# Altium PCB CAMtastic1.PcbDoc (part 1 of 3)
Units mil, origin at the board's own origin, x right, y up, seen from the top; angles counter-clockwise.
Board outline 2031.62 x 893.83 mil, 4 copper layers (Top Layer, Mid-Layer 1, Mid-Layer 2, Bottom Layer); 0 components, 63 nets, 248 pads, 0 vias.
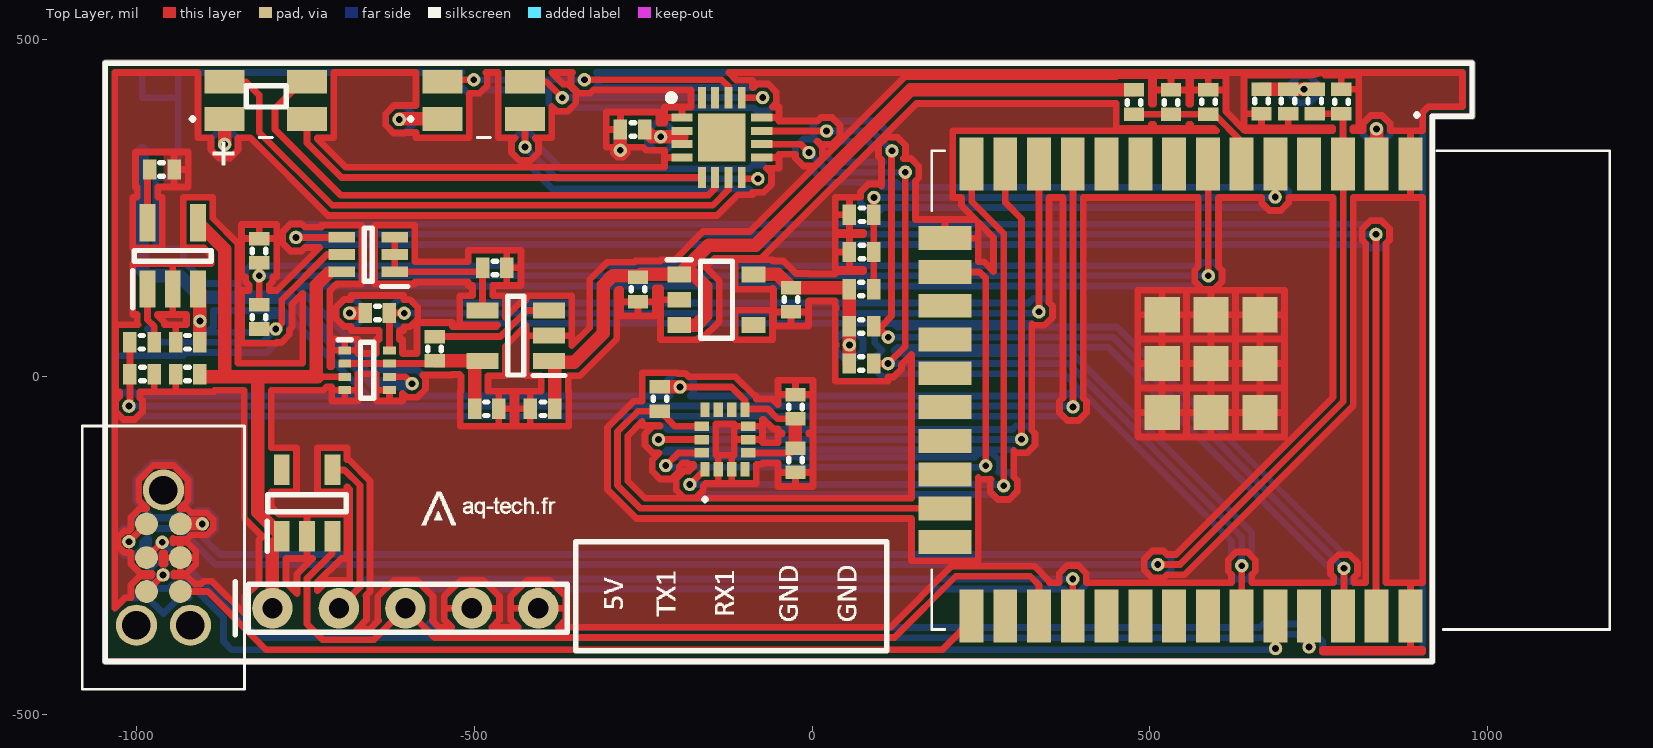
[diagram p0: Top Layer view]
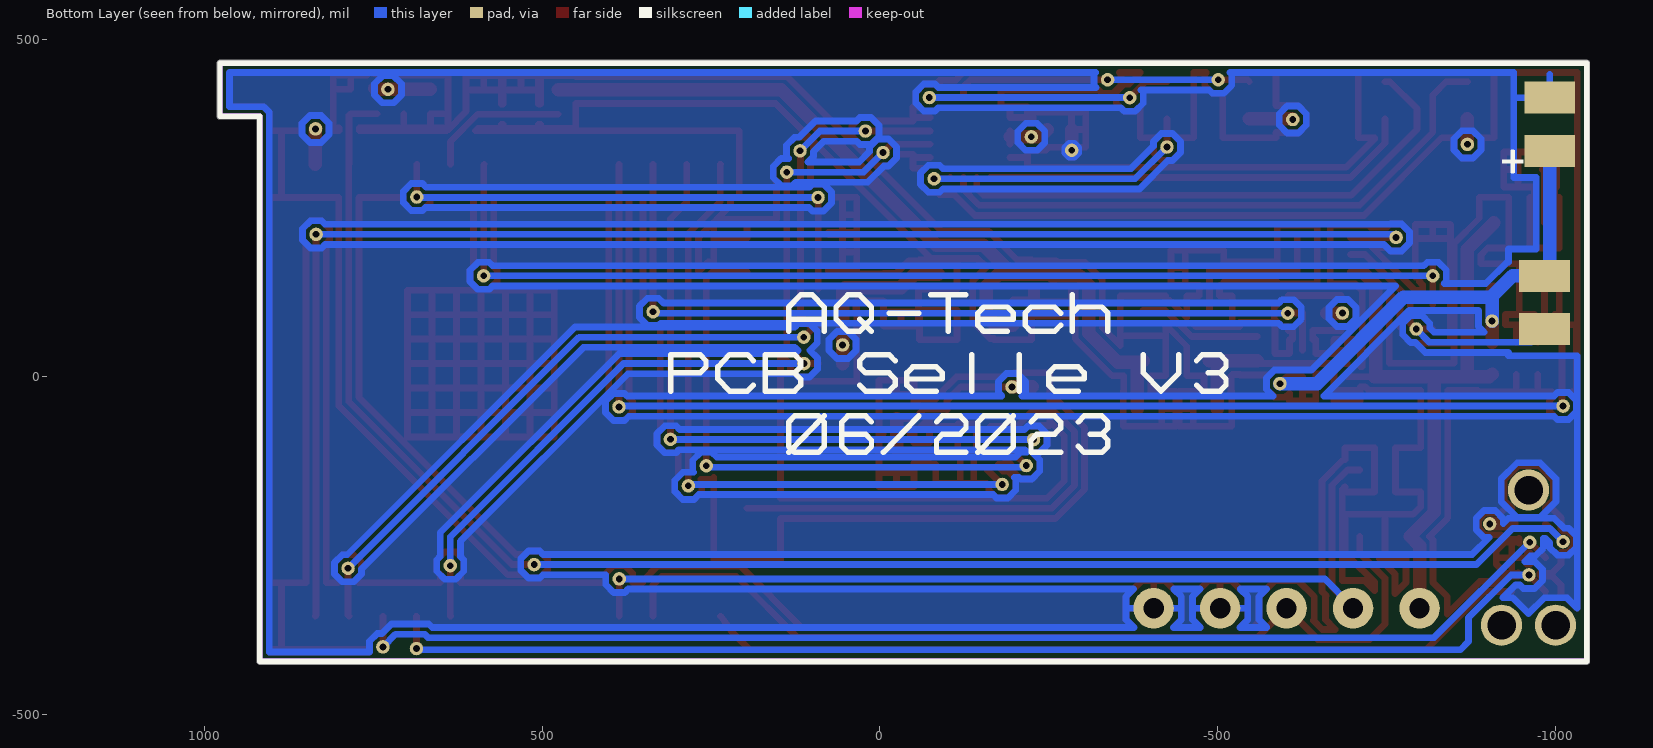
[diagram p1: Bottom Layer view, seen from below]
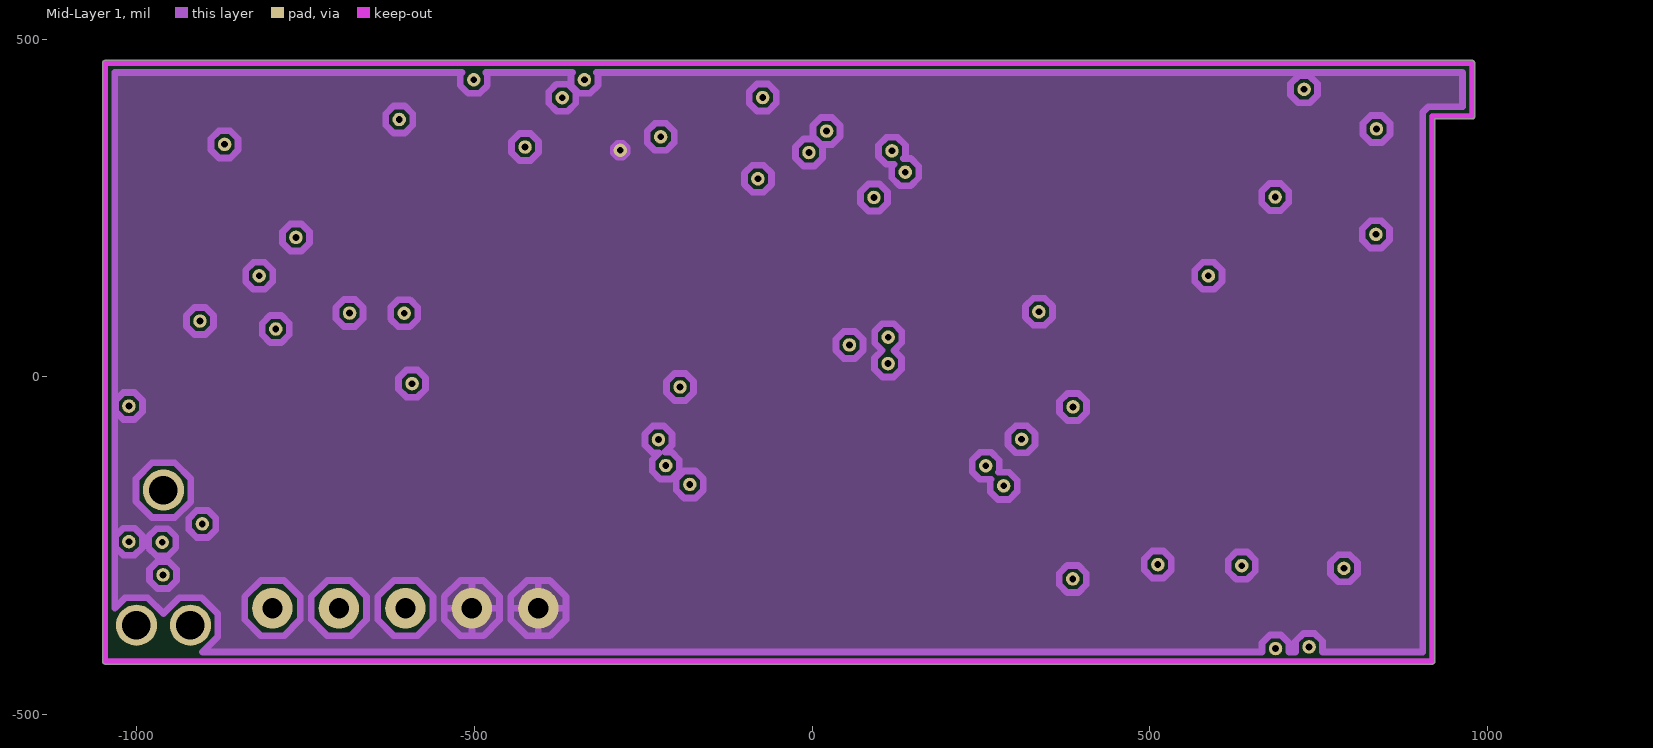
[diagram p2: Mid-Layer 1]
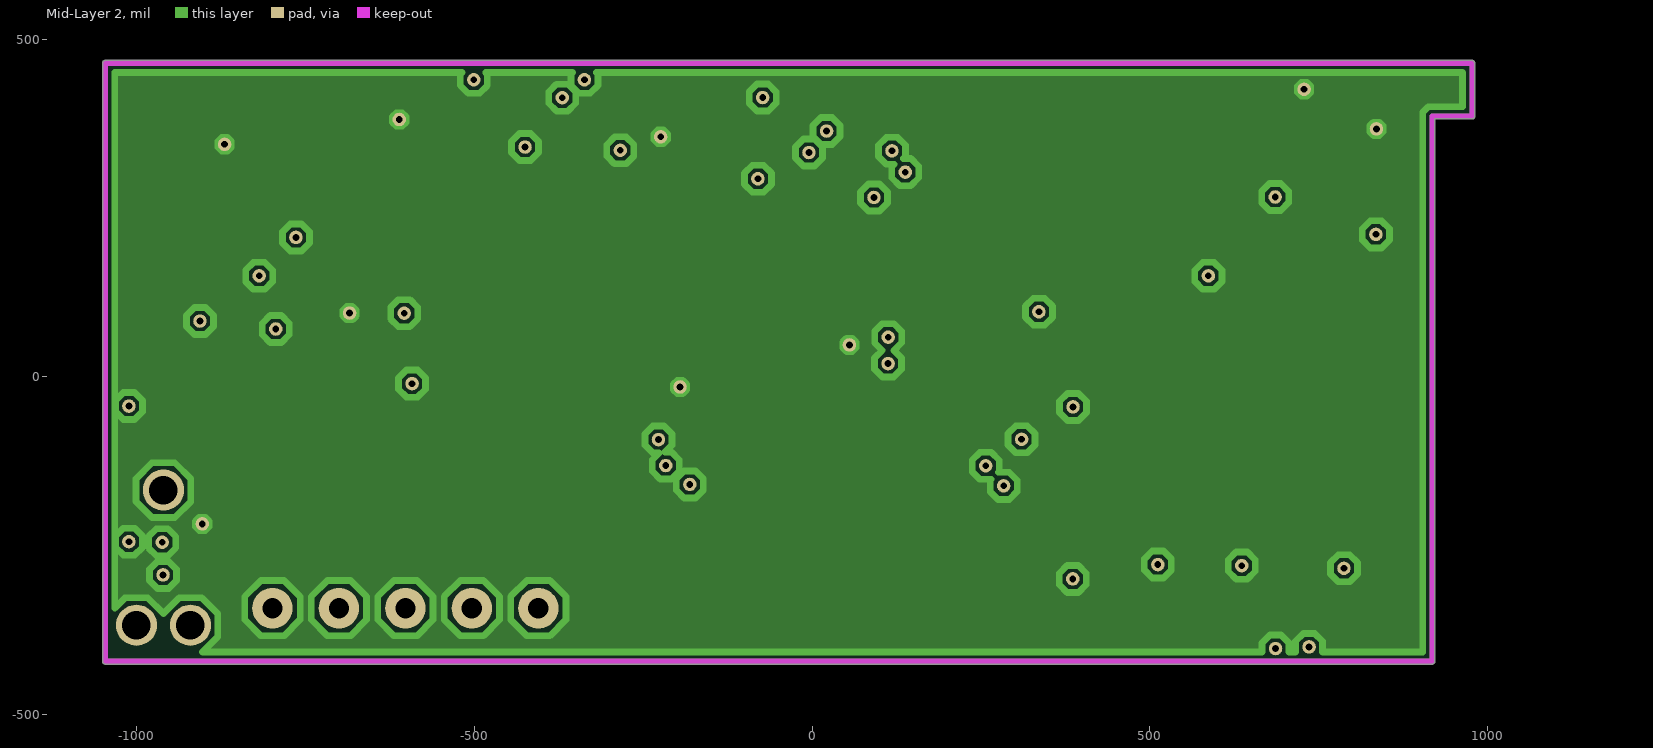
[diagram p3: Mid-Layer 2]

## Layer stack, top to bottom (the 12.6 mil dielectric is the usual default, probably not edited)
Top Solder: solder mask 0.4, Solder Resist, Dk 3.5
Top Layer: signal copper 1.4
Dielectric 1: dielectric 12.6, FR-4, Dk 4.8
Mid-Layer 1: signal copper 1.4
Dielectric 2: dielectric 12.6, FR-4, Dk 4.8
Mid-Layer 2: signal copper 1.4
Dielectric 3: dielectric 12.6, FR-4, Dk 4.8
Bottom Layer: signal copper 1.4
Bottom Solder: solder mask 0.4, Solder Resist, Dk 3.5

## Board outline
-1050.68,-421.26 -1050.68,464.57 cw(c-1046.68,464.57) -1046.68,468.57 976.94,468.57 cw(c976.94,464.57) 980.94,464.57 980.94,385.83 cw(c976.94,385.83) 976.94,381.83 921.89,381.83 921.89,-421.26 cw(c917.89,-421.26) 917.89,-425.26 -1046.68,-425.26 cw(c-1046.68,-421.26)

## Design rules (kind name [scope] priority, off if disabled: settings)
Clearance [All] p1: gap=10 ignorepadtopadclearanceinfootprint=FALSE except(0: Arc-Hole Track-Hole SMDPad-Hole THPad-Hole Via-Hole Fill-Hole Poly-Hole Region-Hole Text-Hole)
PolygonConnect CAM_PolygonConnect_$Net0 [InNet('$Net0')] p1: connectstyle=Direct reliefconductorwidth=10 reliefentries=4 polygonreliefangle="90 Angle" airgapwidth=10
PolygonConnect CAM_PolygonConnect_$Net11 [InNet('$Net11')] p2: connectstyle=Direct reliefconductorwidth=10 reliefentries=4 polygonreliefangle="90 Angle" airgapwidth=10
PolygonConnect [All] p3: connectstyle=Relief reliefconductorwidth=10 reliefentries=4 polygonreliefangle="90 Angle" airgapwidth=10
RoutingVias [All] p1: holewidth=28 width=50 viastyle="Through Hole" minholewidth=28 minwidth=50 maxholewidth=28 maxwidth=50
SolderMaskExpansion [All] p1: expansion=4 istentingtop=FALSE
Width [All] p1: maxlimit=10 minlimit=10 preferedwidth=10
30 further rules are at their usual default settings.

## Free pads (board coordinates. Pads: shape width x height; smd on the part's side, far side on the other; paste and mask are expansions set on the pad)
  round 20 hole 10 mask+24: 1(-1011.81,-244.09) 1(-1011.81,-43.31) 1(-962.48,-244.91) 1(-961.23,-293.31) 1(-906.55,82.68) 1(-903.06,-217.79) 1(-870.06,344.25) 1(-818.9,149.61) 1(-794.33,70.87) 1(-764.5,206.49) 1(-685.04,94.49) 1(-611.52,381.09) 1(-604.13,94.25) 1(-592.46,-10.03) 1(-501.11,439.92) 1(-425.21,340.32) 1(-370.08,413.39) 1(-337.31,439.92) 1(-284.16,335.43) 1(-227.65,-92.85) 1(-224.41,355.38) 1(-216.87,-131.27) 1(-195.71,-15.01) 1(-181.26,-159.32) 1(-80.36,293.32) 1(-73.4,413.63) 1(-4.77,332.17) 1(21.28,364.01) 1(55.12,47.24) 1(91.47,265.6) 1(112.33,19.63) 1(112.48,58.77) 1(118.11,334.65) 1(137.8,303.15) 1(256.91,-131.72) 1(283.46,-161.42) 1(310.04,-92.45) 1(335.66,96.4) 1(385.83,-299.21) 1(386.19,-44.46) 1(511.81,-278) 1(586.61,149.61) 1(636.01,-279.53) 1(685.53,266.32) 1(686.04,-402.28) 1(728.35,425.76) 1(735.7,-399.84) 1(787.4,-283.46) 1(834.65,210.98) 1(835.5,367.15)
  rect 20x30 smd paste+0 mask+24: 1(-1010.18,3.94) 1(-1010.18,51.18) 1(-980.88,307.09) 1(-974.18,3.94) 1(-974.18,51.18) 1(-944.88,307.09) 1(-942.55,3.94) 1(-942.55,51.18) 1(-906.55,3.94) 1(-906.55,51.18) 1(-661.98,94.49) 1(-625.98,94.49) 1(-500,-47.24) 1(-488.19,161.42) 1(-464,-47.24) 1(-452.19,161.42) 1(-417.32,-47.24) 1(-381.32,-47.24) 1(-284.03,366.14) 1(-248.03,366.14) 1(55.12,19.63) 1(55.12,74.74) 1(55.12,129.86) 1(55.12,184.98) 1(55.12,240.1) 1(91.12,19.63) 1(91.12,74.74) 1(91.12,129.86) 1(91.12,184.98) 1(91.12,240.1)
  round 61.02 hole 42.13 mask+3.49: 1(-1000.63,-367.72) 1(-960.63,-167.72) 1(-920.63,-367.72)
  rect 74.8x47.24 smd far side paste+0 mask-3.4: 1(-992.13,334.65) 1(-992.13,413.39) 1(-984.25,70.87) 1(-984.25,149.61)
  round 33.86 smd paste+0 mask+17.07: 1(-985.63,-317.72) 1(-985.63,-267.72) 1(-985.63,-217.72) 1(-935.63,-317.72) 1(-935.63,-267.72) 1(-935.63,-217.72)
  rect 23.62x55.12 smd paste+0 mask+22.19: 1(-984.25,129.92) 1(-984.25,228.35) 1(-946.85,129.92) 1(-909.45,129.92) 1(-909.45,228.35)
  rect 59.05x35.43 smd paste+0 mask+4.47: 1(-870.08,381.89) 1(-870.08,437.01) 1(-748.03,381.89) 1(-748.03,437.01) 1(-547.24,381.89) 1(-547.24,437.01) 1(-425.2,381.89) 1(-425.2,437.01)
  rect 30x20 smd paste+0 mask+19: 1(-818.9,70.87) 1(-818.9,106.87) 1(-818.9,168.72) 1(-818.9,204.72) 1(-559.06,23.62) 1(-559.06,59.62) 1(-257.87,111.13) 1(-257.87,147.13) 1(-225.59,-50.96) 1(-225.59,-14.96) 1(-31.5,96.17) 1(-31.5,132.17) 1(-24.8,-141.51) 1(-24.8,-105.51) 1(-24.8,-62.2) 1(-24.8,-26.2) 1(476.32,388.91) 1(476.32,424.91) 1(531.44,388.91) 1(531.44,424.91) 1(586.55,388.91) 1(586.55,424.91) 1(665.35,389.76) 1(665.35,425.76) 1(704.72,389.76) 1(704.72,425.76) 1(744.09,389.76) 1(744.09,425.76) 1(783.46,389.76) 1(783.46,425.76)
  round 60 hole 30 mask+4: 1(-799.21,-342.52) 1(-700.79,-342.52) 1(-602.36,-342.52) 1(-503.94,-342.52) 1(-405.51,-342.52)
  rect 23.62x45.28 smd paste+0 mask+22.19: 1(-785.43,-236.22) 1(-785.43,-137.8) 1(-748.03,-236.22) 1(-710.63,-236.22) 1(-710.63,-137.8)
  rect 39.37x15.75 smd paste+0 mask+14.31: 1(-696.85,155.51) 1(-696.85,181.1) 1(-696.85,206.69) 1(-618.11,155.51) 1(-618.11,181.1) 1(-618.11,206.69)
  rect 18.9x11.81 smd paste+0 mask+24.55: 1(-692.13,-19.69) 1(-692.13,0) 1(-692.13,19.68) 1(-692.13,39.37) 1(-625.98,-19.69) 1(-625.98,0) 1(-625.98,19.68) 1(-625.98,39.37)
  rect 47.24x23.62 smd paste+0 mask+10.38: 1(-488.19,23.62) 1(-488.19,98.43) 1(-389.76,23.62) 1(-389.76,61.02) 1(-389.76,98.43)
  rect 35.43x23.62 smd paste+0 mask+16.28: 1(-196.85,76.77) 1(-196.85,114.17) 1(-196.85,151.57) 1(-86.61,76.77) 1(-86.61,151.57)
  rect 31.5x11.81 smd paste+0 mask+18.25: 1(-192.91,324.8) 1(-192.91,344.49) 1(-192.91,364.17) 1(-192.91,383.86) 1(-74.8,324.8) 1(-74.8,344.49) 1(-74.8,364.17) 1(-74.8,383.86)
  rect 21.65x13.78 smd paste+0 mask+23.17: 1(-163.78,-112.6) 1(-163.78,-92.91) 1(-163.78,-73.23) 1(-94.49,-112.6) 1(-94.49,-92.91) 1(-94.49,-73.23)
  rect 11.81x31.5 smd paste+0 mask+28.09: 1(-163.39,295.28) 1(-163.39,413.39) 1(-143.7,295.28) 1(-143.7,413.39) 1(-124.02,295.28) 1(-124.02,413.39) 1(-104.33,295.28) 1(-104.33,413.39)
  rect 13.78x21.65 smd paste+0 mask+27.11: 1(-158.66,-137.01) 1(-158.66,-48.82) 1(-138.98,-137.01) 1(-138.98,-48.82) 1(-119.29,-137.01) 1(-119.29,-48.82) 1(-99.61,-137.01) 1(-99.61,-48.82)
  rect 70.87x70.87 smd paste+0 mask-1.43: 1(-133.86,354.33)
  rect 78.74x35.43 smd paste+0 mask-5.37: 1(196.46,-244.69) 1(196.46,-194.69) 1(196.46,-144.69) 1(196.46,-94.69) 1(196.46,-44.69) 1(196.46,5.31) 1(196.46,55.31) 1(196.46,105.31) 1(196.46,155.31) 1(196.46,205.31)
  rect 35.43x78.74 smd paste+0 mask+16.28: 1(235.83,-354.33) 1(235.83,314.96) 1(285.83,-354.33) 1(285.83,314.96) 1(335.83,-354.33) 1(335.83,314.96) 1(385.83,-354.33) 1(385.83,314.96) 1(435.83,-354.33) 1(435.83,314.96) 1(485.83,-354.33) 1(485.83,314.96) 1(535.83,-354.33) 1(535.83,314.96) 1(585.83,-354.33) 1(585.83,314.96) 1(635.83,-354.33) 1(635.83,314.96) 1(685.83,-354.33) 1(685.83,314.96) 1(735.83,-354.33) 1(735.83,314.96) 1(785.83,-354.33) 1(785.83,314.96) 1(835.83,-354.33) 1(835.83,314.96) 1(885.83,-354.33) 1(885.83,314.96)
  rect 52.36x52.36 smd paste+0 mask+7.82: 1(518.11,-52.76) 1(518.11,19.68) 1(518.11,92.13) 1(590.55,-52.76) 1(590.55,19.68) 1(590.55,92.13) 1(662.99,-52.76) 1(662.99,19.68) 1(662.99,92.13)

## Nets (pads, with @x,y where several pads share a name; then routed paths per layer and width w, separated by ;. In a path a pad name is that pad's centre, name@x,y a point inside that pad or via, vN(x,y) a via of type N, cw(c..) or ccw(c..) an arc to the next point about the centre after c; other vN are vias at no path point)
$Net0: pad.1@55.12,19.63 pad.1@55.12,47.24 pad.1@55.12,74.74 pad.1@55.12,129.86 pad.1@665.35,425.76 pad.1@704.72,425.76 pad.1@728.35,425.76 pad.1@744.09,425.76 pad.1@835.5,367.15 pad.1@835.83,314.96 pad.1@-24.8,-62.2 pad.1@-24.8,-105.51 pad.1@-31.5,132.17 pad.1@-86.61,151.57 pad.1@-94.49,-112.6 pad.1@-99.61,-48.82 pad.1@-192.91,344.49 pad.1@-192.91,364.17 pad.1@-195.71,-15.01 pad.1@-224.41,355.38 pad.1@-225.59,-14.96 pad.1@-248.03,366.14 pad.1@-547.24,381.89 pad.1@-611.52,381.09 pad.1@-661.98,94.49 pad.1@-685.04,94.49 pad.1@-870.06,344.25 pad.1@-870.08,381.89 pad.1@-903.06,-217.79 pad.1@-935.63,-217.72 | length 13937.4
  Top Layer w10: pad.1@-195.71,-15.01 -119.5,-15.01 -99.61,-34.9 pad.1@-99.61,-47.75 ; pad.1@-192.91,344.49 -192.91,349.05 -192.91,355.38 pad.1@-192.91,364.17 ; pad.1@-99.61,-48.82 pad.1@-99.61,-47.75 ; pad.1@-94.49,-112.6 -31.89,-112.6 pad.1@-24.8,-105.51 ; pad.1@-24.8,-62.2 -51.04,-62.2 -65.5,-47.75 pad.1@-99.61,-47.75
  Top Layer w20: pad.1@-935.63,-217.72 -903.13,-217.72 pad.1@-903.06,-217.79 ; pad.1@-870.06,344.25 pad.1@-870.08,381.89 ; pad.1@-685.04,94.49 pad.1@-661.98,94.49 ; pad.1@-611.52,381.09 -610.72,381.89 pad.1@-547.24,381.89 ; pad.1@-248.03,366.14 -237.27,355.38 pad.1@-224.41,355.38 -192.91,355.38 ; pad.1@-225.59,-14.96 -195.77,-14.96 pad.1@-195.71,-15.01 ; pad.1@-86.61,151.57 -50.9,151.57 pad.1@-31.5,132.17 51.5,132.17 pad.1@55.12,129.86 pad.1@55.12,74.74 pad.1@55.12,47.24 pad.1@55.12,19.63 ; pad.1@-24.8,-105.51 pad.1@-24.8,-62.2 ; pad.1@665.35,425.76 pad.1@704.72,425.76 pad.1@728.35,425.76 746.51,425.76 747.74,426.99 pad.1@744.09,425.76 ; pad.1@835.5,367.15 835.83,366.83 pad.1@835.83,314.96
  Mid-Layer 2 w10: -1032.68,-342.47 -1032.68,450.57 -518.74,450.57 -521.11,448.2 -521.11,431.63 -509.39,419.92 -492.82,419.92 -481.11,431.63 -481.11,448.2 -483.47,450.57 -354.94,450.57 -357.31,448.2 -357.31,431.63 -345.59,419.92 -329.02,419.92 -317.31,431.63 -317.31,448.2 -319.67,450.57 962.94,450.57 962.94,399.83 912.09,399.83 903.89,391.63 903.89,-407.26 755.7,-407.26 755.7,-391.55 743.99,-379.84 727.42,-379.84 715.7,-391.55 715.7,-407.26 706.04,-407.26 706.04,-393.99 694.33,-382.28 677.76,-382.28 666.04,-393.99 666.04,-407.26 -902.88,-407.26 -880.12,-384.5 -880.12,-350.94 -903.85,-327.21 -937.41,-327.21 -960.63,-350.42 -983.85,-327.21 -1017.41,-327.21 -1032.68,-342.47 ; -1031.81,-252.38 -1020.1,-264.09 -1003.53,-264.09 -991.81,-252.38 -991.81,-235.81 -1003.53,-224.09 -1020.1,-224.09 -1031.81,-235.81 -1031.81,-252.38 ; -1031.81,-51.59 -1020.1,-63.31 -1003.53,-63.31 -991.81,-51.59 -991.81,-35.02 -1003.53,-23.31 -1020.1,-23.31 -1031.81,-35.02 -1031.81,-51.59 ; -1001.14,-184.5 -977.41,-208.23 -943.85,-208.23 -920.12,-184.5 -920.12,-150.94 -943.85,-127.21 -977.41,-127.21 -1001.14,-150.94 -1001.14,-184.5 ; -982.48,-253.19 -970.76,-264.91 -954.19,-264.91 -942.48,-253.19 -942.48,-236.62 -954.19,-224.91 -970.76,-224.91 -982.48,-236.62 -982.48,-253.19 ; -981.23,-301.59 -969.51,-313.31 -952.94,-313.31 -941.23,-301.59 -941.23,-285.02 -952.94,-273.31 -969.51,-273.31 -981.23,-285.02 -981.23,-301.59 ; -926.55,74.39 -914.84,62.68 -898.27,62.68 -886.55,74.39 -886.55,90.96 -898.27,102.68 -914.84,102.68 -926.55,90.96 -926.55,74.39 ; -913.06,-221.93 -907.2,-227.79 -898.92,-227.79 -893.06,-221.93 -893.06,-213.65 -898.92,-207.79 -907.2,-207.79 -913.06,-213.65 -913.06,-221.93 ; -880.06,340.11 -874.2,334.25 -865.92,334.25 -860.06,340.11 -860.06,348.39 -865.92,354.25 -874.2,354.25 -880.06,348.39 -880.06,340.11 ; -840.21,-359.5 -816.2,-383.52 -782.23,-383.52 -758.21,-359.5 -758.21,-325.54 -782.23,-301.52 -816.2,-301.52 -840.21,-325.54 -840.21,-359.5 ; -838.9,141.32 -827.18,129.61 -810.61,129.61 -798.9,141.32 -798.9,157.89 -810.61,169.61 -827.18,169.61 -838.9,157.89 -838.9,141.32 ; -814.33,62.58 -802.62,50.87 -786.05,50.87 -774.34,62.58 -774.34,79.15 -786.05,90.87 -802.62,90.87 -814.33,79.15 -814.33,62.58 ; -784.5,198.2 -772.78,186.49 -756.22,186.49 -744.5,198.2 -744.5,214.77 -756.22,226.48 -772.78,226.48 -784.5,214.77 -784.5,198.2 ; -741.79,-359.5 -717.77,-383.52 -683.8,-383.52 -659.79,-359.5 -659.79,-325.54 -683.8,-301.52 -717.77,-301.52 -741.79,-325.54 -741.79,-359.5 ; -695.04,90.35 -689.18,84.49 -680.9,84.49 -675.04,90.35 -675.04,98.63 -680.9,104.49 -689.18,104.49 -695.04,98.63 -695.04,90.35 ; -643.36,-359.5 -619.34,-383.52 -585.38,-383.52 -561.36,-359.5 -561.36,-325.54 -585.38,-301.52 -619.34,-301.52 -643.36,-325.54 -643.36,-359.5 ; -624.13,85.96 -612.41,74.25 -595.84,74.25 -584.13,85.96 -584.13,102.53 -595.84,114.25 -612.41,114.25 -624.13,102.53 -624.13,85.96 ; -621.52,376.95 -615.66,371.09 -607.38,371.09 -601.52,376.95 -601.52,385.23 -607.38,391.09 -615.66,391.09 -621.52,385.23 -621.52,376.95 ; -612.46,-18.31 -600.75,-30.03 -584.18,-30.03 -572.46,-18.31 -572.46,-1.74 -584.18,9.97 -600.75,9.97 -612.46,-1.74 -612.46,-18.31 ; -544.94,-359.5 -520.92,-383.52 -486.95,-383.52 -462.94,-359.5 -462.94,-325.54 -486.95,-301.52 -520.92,-301.52 -544.94,-325.54 -544.94,-359.5 ; -446.51,-359.5 -422.49,-383.52 -388.53,-383.52 -364.51,-359.5 -364.51,-325.54 -388.53,-301.52 -422.49,-301.52 -446.51,-325.54 -446.51,-359.5 ; -445.21,332.04 -433.49,320.32 -416.92,320.32 -405.21,332.04 -405.21,348.61 -416.92,360.32 -433.49,360.32 -445.21,348.61 -445.21,332.04 ; -390.08,405.1 -378.36,393.39 -361.79,393.39 -350.08,405.1 -350.08,421.67 -361.79,433.39 -378.36,433.39 -390.08,421.67 -390.08,405.1 ; -304.16,327.15 -292.45,315.44 -275.88,315.44 -264.16,327.15 -264.16,343.72 -275.88,355.43 -292.45,355.43 -304.16,343.72 -304.16,327.15 ; -247.65,-101.13 -247.65,-84.56 -235.93,-72.85 -219.36,-72.85 -207.65,-84.56 -207.65,-101.13 -217.79,-111.27 -208.58,-111.27 -196.87,-122.99 -196.87,-139.56 -208.58,-151.27 -225.15,-151.27 -236.87,-139.56 -236.87,-122.99 -226.72,-112.85 -235.93,-112.85 -247.65,-101.13 ; -234.41,351.24 -228.55,345.38 -220.27,345.38 -214.41,351.24 -214.41,359.52 -220.27,365.38 -228.55,365.38 -234.41,359.52 -234.41,351.24 ; -205.71,-19.16 -199.86,-25.01 -191.57,-25.01 -185.71,-19.16 -185.71,-10.87 -191.57,-5.01 -199.86,-5.01 -205.71,-10.87 -205.71,-19.16 ; -201.26,-167.6 -189.55,-179.32 -172.98,-179.32 -161.26,-167.6 -161.26,-151.03 -172.98,-139.32 -189.55,-139.32 -201.26,-151.03 -201.26,-167.6 ; -100.36,285.04 -88.65,273.32 -72.08,273.32 -60.36,285.04 -60.36,301.6 -72.08,313.32 -88.65,313.32 -100.36,301.6 -100.36,285.04 ; -93.4,405.34 -81.69,393.63 -65.12,393.63 -53.4,405.34 -53.4,421.91 -65.12,433.63 -81.69,433.63 -93.4,421.91 -93.4,405.34 ; -24.77,323.89 -13.06,312.17 3.51,312.17 15.23,323.89 15.23,340.45 3.51,352.17 -13.06,352.17 -24.77,340.45 -24.77,323.89 ; 1.28,355.72 12.99,344.01 29.56,344.01 41.28,355.72 41.28,372.29 29.56,384.01 12.99,384.01 1.28,372.29 1.28,355.72 ; 45.12,43.1 50.98,37.24 59.26,37.24 65.12,43.1 65.12,51.39 59.26,57.24 50.98,57.24 45.12,51.39 45.12,43.1 ; 71.47,257.32 83.18,245.6 99.75,245.6 111.46,257.32 111.46,273.88 99.75,285.6 83.18,285.6 71.47,273.88 71.47,257.32 ; 92.33,11.34 92.33,27.91 103.69,39.27 92.48,50.48 92.48,67.05 104.2,78.77 120.76,78.77 132.48,67.05 132.48,50.48 121.12,39.12 132.33,27.91 132.33,11.34 120.61,-0.37 104.05,-0.37 92.33,11.34 ; 98.11,326.36 98.11,342.93 109.83,354.65 126.39,354.65 138.11,342.93 138.11,326.36 134.9,323.15 146.08,323.15 157.79,311.43 157.79,294.87 146.08,283.15 129.51,283.15 117.8,294.87 117.8,311.43 121.01,314.65 109.83,314.65 98.11,326.36 ; 236.91,-140 236.91,-123.43 248.62,-111.72 265.19,-111.72 276.91,-123.43 276.91,-140 275.49,-141.42 291.75,-141.42 303.46,-153.13 303.46,-169.7 291.75,-181.42 275.18,-181.42 263.46,-169.7 263.46,-153.13 264.88,-151.72 248.62,-151.72 236.91,-140 ; 290.04,-100.73 301.75,-112.45 318.32,-112.45 330.04,-100.73 330.04,-84.16 318.32,-72.45 301.75,-72.45 290.04,-84.16 290.04,-100.73 ; 315.66,88.11 327.37,76.4 343.94,76.4 355.66,88.11 355.66,104.68 343.94,116.4 327.37,116.4 315.66,104.68 315.66,88.11 ; 365.83,-307.5 377.54,-319.21 394.11,-319.21 405.83,-307.5 405.83,-290.93 394.11,-279.21 377.54,-279.21 365.83,-290.93 365.83,-307.5 ; 366.19,-52.75 377.91,-64.46 394.48,-64.46 406.19,-52.75 406.19,-36.18 394.48,-24.46 377.91,-24.46 366.19,-36.18 366.19,-52.75 ; 491.81,-286.29 503.53,-298 520.1,-298 531.81,-286.29 531.81,-269.72 520.1,-258 503.53,-258 491.81,-269.72 491.81,-286.29 ; 566.61,141.32 578.33,129.61 594.9,129.61 606.61,141.32 606.61,157.89 594.9,169.61 578.33,169.61 566.61,157.89 566.61,141.32 ; 616.02,-287.81 627.73,-299.53 644.3,-299.53 656.01,-287.81 656.01,-271.24 644.3,-259.53 627.73,-259.53 616.02,-271.24 616.02,-287.81 ; 665.53,258.04 677.25,246.32 693.82,246.32 705.53,258.04 705.53,274.61 693.82,286.32 677.25,286.32 665.53,274.61 665.53,258.04 ; 718.35,421.62 724.2,415.76 732.49,415.76 738.35,421.62 738.35,429.91 732.49,435.76 724.2,435.76 718.35,429.91 718.35,421.62 ; 767.4,-291.75 779.12,-303.46 795.69,-303.46 807.4,-291.75 807.4,-275.18 795.69,-263.46 779.12,-263.46 767.4,-275.18 767.4,-291.75 ; 814.65,202.7 826.36,190.98 842.93,190.98 854.65,202.7 854.65,219.27 842.93,230.98 826.36,230.98 814.65,219.27 814.65,202.7 ; 825.5,363.01 831.36,357.15 839.65,357.15 845.5,363.01 845.5,371.29 839.65,377.15 831.36,377.15 825.5,371.29 825.5,363.01
$Net1: pad.1@-592.46,-10.03 pad.1@-625.98,0 pad.1@-906.55,51.18 pad.1@-906.55,82.68 pad.1@-909.45,129.92 pad.1@-984.25,149.61 pad.1@-992.13,334.65 | length 799.9
  Top Layer w10: pad.1@-625.98,0 -602.49,0 pad.1@-592.46,-10.03
  Top Layer w20: pad.1@-909.45,129.92 -906.55,127.03 pad.1@-906.55,82.68 pad.1@-906.55,51.18
  Bottom Layer w20: pad.1@-992.13,334.65 -992.13,157.48 pad.1@-984.25,149.61 -937.01,149.61 -906.55,119.15 -906.55,118.11 ; pad.1@-906.55,82.68 -906.55,118.11 ; pad.1@-592.46,-10.03 -647.45,-10.03 -775.59,118.11 -906.55,118.11
$Net2: pad.1@-696.85,181.1 pad.1@-794.33,70.87 pad.1@-818.9,70.87 pad.1@-984.25,70.87 | length 394
  Top Layer w10: pad.1@-818.9,70.87 pad.1@-794.33,70.87 -785.31,79.89 -785.31,114.17 -718.37,181.1 pad.1@-696.85,181.1
  Bottom Layer w10: pad.1@-984.25,70.87 -964.57,51.18 -814.02,51.18 pad.1@-794.33,70.87
$Net3: pad.1@-124.02,413.39 pad.1@-337.31,439.92 pad.1@-501.11,439.92 pad.1@-547.24,437.01 | length 445.1
  Top Layer w10: pad.1@-547.24,437.01 -544.34,439.92 pad.1@-501.11,439.92 ; pad.1@-337.31,439.92 -134.07,439.92 -124.02,429.86 pad.1@-124.02,413.39
  Bottom Layer w10: pad.1@-501.11,439.92 pad.1@-337.31,439.92
$Net4: pad.1@-73.4,413.63 pad.1@-104.33,413.39 pad.1@-370.08,413.39 pad.1@-425.2,437.01 | length 392.7
  Top Layer w10: pad.1@-425.2,437.01 -393.7,437.01 pad.1@-370.08,413.39 ; pad.1@-104.33,413.39 -73.64,413.39 pad.1@-73.4,413.63
  Bottom Layer w10: pad.1@-370.08,413.39 -369.84,413.63 pad.1@-73.4,413.63
$Net5: pad.1@385.83,-299.21 pad.1@385.83,-354.33 pad.1@-700.79,-342.52 pad.1@-710.63,-137.8 | length 1405.4
  Top Layer w10: pad.1@-710.63,-137.8 -692.4,-137.8 -669.74,-160.46 -669.74,-311.47 pad.1@-700.79,-342.52 ; pad.1@385.83,-354.33 pad.1@385.83,-299.21
  Bottom Layer w10: pad.1@-700.79,-342.52 -672.42,-312.52 -659.11,-299.21 pad.1@385.83,-299.21
$Net6: pad.1@685.83,-354.33 pad.1@686.04,-402.28 pad.1@-961.23,-293.31 pad.1@-985.63,-317.72 | length 1798.3
  Top Layer w10: pad.1@-985.63,-317.72 pad.1@-961.23,-293.31 ; pad.1@685.83,-354.33 686.04,-354.55 pad.1@686.04,-402.28
  Bottom Layer w10: pad.1@-961.23,-293.31 -934.96,-293.31 -871.67,-356.6 -871.67,-391.96 -859.48,-404.15 686.04,-404.15 pad.1@686.04,-402.28
$Net7: pad.1@735.7,-399.84 pad.1@735.83,-354.33 pad.1@-962.48,-244.91 pad.1@-985.63,-267.72 | length 1844.9
  Top Layer w10: pad.1@-985.63,-267.72 -962.82,-244.91 pad.1@-962.48,-244.91 ; pad.1@735.7,-399.84 735.7,-354.45 pad.1@735.83,-354.33
  Bottom Layer w10: pad.1@-962.48,-244.91 -962.18,-244.91 -820.86,-386.23 668.89,-386.23 674.13,-380.99 716.85,-380.99 pad.1@735.7,-399.84
$Net8: pad.1@196.46,155.31 pad.1@256.91,-131.72 pad.1@-163.78,-112.6 pad.1@-216.87,-131.27 | length 878.9
  Top Layer w10: pad.1@-216.87,-131.27 -198.19,-112.6 pad.1@-163.78,-112.6 ; pad.1@196.46,155.31 196.53,155.39 247.89,155.39 256.91,146.37 pad.1@256.91,-131.72
  Bottom Layer w10: pad.1@-216.87,-131.27 -214.28,-133.86 254.77,-133.86 pad.1@256.91,-131.72
$Net9: pad.1@235.83,314.96 pad.1@283.46,-161.42 pad.1@-158.66,-137.01 pad.1@-181.26,-159.32 | length 993.5
  Top Layer w10: pad.1@-181.26,-159.32 -180.97,-159.32 pad.1@-158.66,-137.01 ; pad.1@235.83,314.96 236.22,314.57 236.22,259.84 283.46,212.6 pad.1@283.46,-161.42
  Bottom Layer w10: pad.1@-181.26,-159.32 281.37,-159.32 pad.1@283.46,-161.42
$Net10: pad.1@285.83,314.96 pad.1@310.04,-92.45 pad.1@-163.78,-92.91 pad.1@-227.65,-92.85 | length 1019.2
  Top Layer w10: pad.1@-227.65,-92.85 -227.58,-92.91 pad.1@-163.78,-92.91 ; pad.1@285.83,314.96 285.95,314.84 285.95,258.17 310.04,234.08 pad.1@310.04,-92.45
  Bottom Layer w10: pad.1@-227.65,-92.85 309.63,-92.85 pad.1@310.04,-92.45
